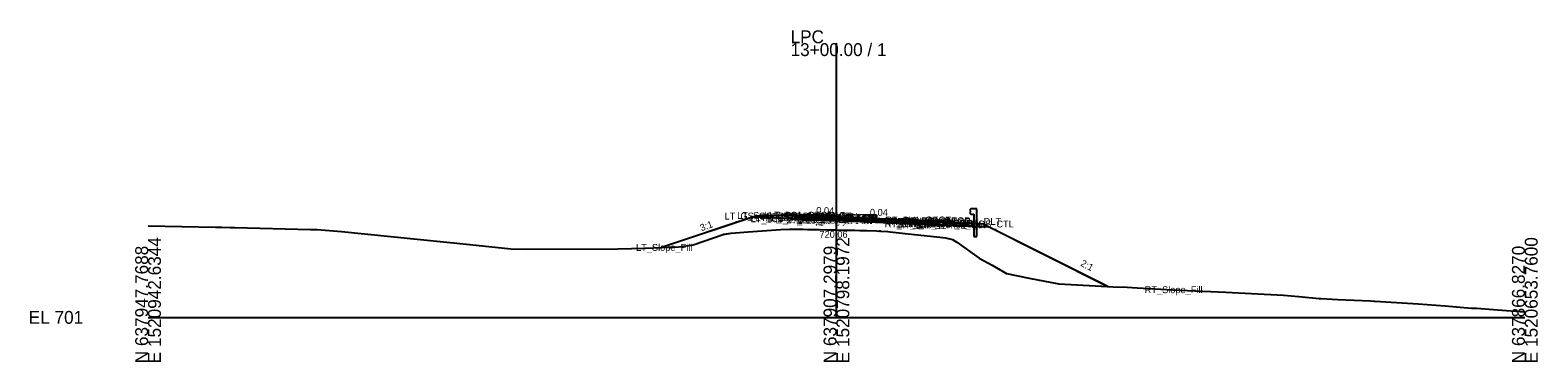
# Model space of a CAD drawing. Extents: x -26 to 303, y -10 to 4521.
# Drawn here: x -25.7 to 302.8, y 2990.3 to 3062.6 of the extents above; entities that cross this region are included whole.
import ezdxf

# ---------------------------------------------------------------- set-up
doc = ezdxf.new("R2010")
doc.units = 0
for name, color, linetype in [('Default', 7, 'Continuous'), ('Exist Cross Section Cell', 7, 'Continuous'), ('Exist XS Center Line Elevation Label', 7, 'Continuous'), ('Exist XS Ground Line', 7, 'Continuous'), ('Prop CMT Guardrail Graphics', 7, 'Continuous'), ('Prop CMT Pvmt Course 1', 7, 'Continuous'), ('Prop CMT Pvmt Course 2', 7, 'Continuous'), ('Prop CMT Pvmt Course 3', 7, 'Continuous'), ('Prop CMT Pvmt Surface', 7, 'Continuous'), ('Prop CMT Pvmt Surface Shoulder', 7, 'Continuous'), ('Prop CMT Shld Paved Course 1', 7, 'Continuous'), ('Prop CMT Shld Paved Course 2', 7, 'Continuous'), ('Prop CMT Shld Paved Course 3', 7, 'Continuous'), ('Prop CMT Slope Grass', 7, 'Continuous'), ('Prop CMT Subgrade Earthwork', 7, 'Continuous'), ('Prop XS Earthwork Shape', 7, 'Continuous'), ('Prop XS Shear Point Element', 7, 'Continuous')]:
    doc.layers.add(name, color=color, linetype=linetype)

msp = doc.modelspace()

# ---------------------------------------------------------------- linework, layer by layer
at = {"layer": 'Exist Cross Section Cell'}
for p, q in [((150, 3000), (150, 3059.75)), ((0, 3000), (150, 3000)), ((150, 3000), (300, 3000))]:
    msp.add_line(p, q, dxfattribs=at)
at = {"layer": 'Exist XS Ground Line'}
msp.add_lwpolyline([(0, 3019.92), (14.67, 3019.67), (16.1, 3019.64), (17.96, 3019.62), (18.33, 3019.61), (18.91, 3019.6), (35.42, 3019.16), (36.83, 3019.17), (42.14, 3018.71), (70.12, 3015.86), (79.08, 3014.96), (82.44, 3014.84), (102.36, 3014.94), (108.32, 3015.11), (115.64, 3015.35), (118.75, 3015.83), (125.3, 3018.08), (125.32, 3018.09), (125.33, 3018.09), (125.36, 3018.1), (127.06, 3018.33), (130.75, 3018.65), (137.87, 3019.12), (139.76, 3019.25), (140.14, 3019.23), (141.08, 3019.2), (141.4, 3019.2), (142.44, 3019.21), (142.74, 3019.2), (143.67, 3019.17), (145.33, 3019.14), (146.27, 3019.13), (147.93, 3019.1), (148.85, 3019.09), (150, 3019.06), (151.2, 3019.04), (151.43, 3019.04), (153.4, 3018.99), (154.02, 3018.97), (155.11, 3018.94), (156.61, 3018.9), (158.72, 3018.83), (159.21, 3018.82), (159.48, 3018.83), (159.51, 3018.83), (159.67, 3018.82), (161.12, 3018.73), (161.21, 3018.73), (161.73, 3018.66), (165.65, 3018.22), (171.91, 3017.52), (173.77, 3017.3), (175.29, 3016.98), (176.22, 3016.37), (181.12, 3012.93), (183.96, 3011.38), (187.08, 3009.58), (192, 3008.58), (198.46, 3007.32), (210.3, 3006.69), (213.38, 3006.55), (215.54, 3006.43), (223.32, 3006), (228.1, 3005.79), (228.96, 3005.74), (229.84, 3005.71), (234.83, 3005.47), (247.41, 3004.87), (250.76, 3004.53), (255.22, 3004.14), (255.41, 3004.12), (255.65, 3004.1), (259.27, 3003.93), (266.38, 3003.58), (267.13, 3003.54), (267.37, 3003.53), (276.78, 3002.97), (282.67, 3002.49), (288.41, 3002.04), (289.55, 3001.98), (294.04, 3001.63), (300, 3001.2)], dxfattribs=at)
at = {"layer": 'Prop CMT Guardrail Graphics'}
for points in [[(180.6, 3023.65), (179.27, 3023.65), (179, 3023.36)], [(179, 3023.36), (179.27, 3023.07)], [(179.27, 3023.07), (179, 3022.77)], [(179, 3022.77), (179.27, 3022.48), (179.94, 3022.48)], [(180.6, 3017.65), (180.6, 3023.65)], [(179.94, 3022.48), (179.94, 3017.65)], [(179.94, 3017.65), (180.6, 3017.65)]]:
    msp.add_lwpolyline(points, dxfattribs=at)
at = {"layer": 'Prop CMT Pvmt Course 1'}
for points in [[(150.09, 3021.91), (145.42, 3022.1)], [(145.42, 3022.1), (145.42, 3021.85)], [(145.42, 3021.85), (150.09, 3021.66)], [(150.09, 3021.66), (150.09, 3021.91)], [(150.09, 3021.91), (166.95, 3021.23)], [(150.09, 3021.66), (150.09, 3021.91)], [(166.95, 3020.98), (150.09, 3021.66)], [(166.95, 3021.23), (166.95, 3020.98)]]:
    msp.add_lwpolyline(points, dxfattribs=at)
msp.add_lwpolyline([(150.09, 3021.66), (150.09, 3021.78), (150.09, 3021.78), (150.09, 3021.66)], close=True, dxfattribs=at)
msp.add_lwpolyline([(150.09, 3021.66), (150.09, 3021.78), (150.09, 3021.78), (150.09, 3021.66)], close=True, dxfattribs=at)
at = {"layer": 'Prop CMT Pvmt Course 2'}
for points in [[(150.09, 3021.66), (145.42, 3021.85)], [(145.42, 3021.85), (145.42, 3021.52)], [(145.42, 3021.52), (150.09, 3021.33)], [(150.09, 3021.33), (150.09, 3021.66)], [(150.09, 3021.33), (150.09, 3021.66)], [(150.09, 3021.66), (166.95, 3020.98)], [(166.95, 3020.65), (150.09, 3021.33)], [(166.95, 3020.98), (166.95, 3020.65)]]:
    msp.add_lwpolyline(points, dxfattribs=at)
at = {"layer": 'Prop CMT Pvmt Course 3'}
for points in [[(150.09, 3021.33), (145.42, 3021.52)], [(145.42, 3021.52), (145.42, 3021.27)], [(145.42, 3021.27), (150.09, 3021.08)], [(150.09, 3021.08), (150.09, 3021.33)], [(150.09, 3021.33), (166.95, 3020.65)], [(150.09, 3021.08), (150.09, 3021.33)], [(166.95, 3020.4), (150.09, 3021.08)], [(166.95, 3020.65), (166.95, 3020.4)]]:
    msp.add_lwpolyline(points, dxfattribs=at)
at = {"layer": 'Prop CMT Pvmt Surface'}
for points in [[(150.09, 3021.91), (145.42, 3022.1)], [(150.09, 3021.91), (166.95, 3021.23)]]:
    msp.add_lwpolyline(points, dxfattribs=at)
at = {"layer": 'Prop CMT Pvmt Surface Shoulder'}
for points in [[(145.42, 3022.1), (141.43, 3022.26)], [(166.95, 3021.23), (170.94, 3021.07)]]:
    msp.add_lwpolyline(points, dxfattribs=at)
at = {"layer": 'Prop CMT Shld Paved Course 1'}
for p in [(171.21, 3020.81), (179, 3020.55)]:
    msp.add_line(p, (179, 3020.3), dxfattribs=at)
for points in [[(145.42, 3022.1), (141.43, 3022.26), (141.19, 3022.01)], [(141.19, 3022.01), (145.42, 3021.85)], [(145.42, 3021.85), (145.42, 3022.1)], [(166.95, 3021.23), (170.94, 3021.07), (171.21, 3020.81)], [(166.95, 3020.98), (166.95, 3021.23)], [(171.21, 3020.81), (166.95, 3020.98)]]:
    msp.add_lwpolyline(points, dxfattribs=at)
at = {"layer": 'Prop CMT Shld Paved Course 2'}
for points in [[(145.42, 3021.85), (141.19, 3022.01), (140.87, 3021.7)], [(140.87, 3021.7), (145.42, 3021.52)], [(145.42, 3021.52), (145.42, 3021.85)], [(166.95, 3020.98), (171.21, 3020.81), (171.55, 3020.47)], [(166.95, 3020.65), (166.95, 3020.98)], [(171.55, 3020.47), (166.95, 3020.65)]]:
    msp.add_lwpolyline(points, dxfattribs=at)
at = {"layer": 'Prop CMT Shld Paved Course 3'}
for p, q in [((140.87, 3021.7), (140.63, 3021.46)), ((171.55, 3020.47), (171.81, 3020.21))]:
    msp.add_line(p, q, dxfattribs=at)
for points in [[(140.13, 3021.48), (145.42, 3021.27)], [(145.42, 3021.52), (140.87, 3021.7), (140.63, 3021.46)], [(145.42, 3021.27), (145.42, 3021.52)], [(166.95, 3020.4), (166.95, 3020.65)], [(166.95, 3020.65), (171.55, 3020.47), (171.81, 3020.21)], [(172.31, 3020.19), (166.95, 3020.4)]]:
    msp.add_lwpolyline(points, dxfattribs=at)
at = {"layer": 'Prop CMT Slope Grass'}
for points in [[(141.43, 3022.26), (132.44, 3022.08), (111.91, 3015.23)], [(170.94, 3021.07), (181.96, 3020.36), (209.17, 3006.75)]]:
    msp.add_lwpolyline(points, dxfattribs=at)
at = {"layer": 'Prop CMT Subgrade Earthwork'}
for points in [[(145.42, 3021.27), (131.66, 3021.82)], [(150.09, 3021.08), (145.42, 3021.27)], [(150.09, 3021.08), (166.95, 3020.4)], [(166.95, 3020.4), (183.17, 3019.75)]]:
    msp.add_lwpolyline(points, dxfattribs=at)
at = {"layer": 'Prop XS Earthwork Shape'}
msp.add_lwpolyline([(141.08, 3019.2), (141.4, 3019.2), (142.44, 3019.21), (142.74, 3019.2), (143.67, 3019.17), (145.33, 3019.14), (146.27, 3019.13), (147.93, 3019.1), (148.85, 3019.09), (150, 3019.06), (151.2, 3019.04), (151.43, 3019.04), (153.4, 3018.99), (154.02, 3018.97), (155.11, 3018.94), (156.61, 3018.9), (158.72, 3018.83), (159.21, 3018.82), (159.51, 3018.83), (159.67, 3018.82), (161.12, 3018.73), (161.73, 3018.66), (165.65, 3018.22), (171.91, 3017.52), (173.77, 3017.3), (175.29, 3016.98), (176.22, 3016.37), (181.12, 3012.93), (183.96, 3011.38), (187.08, 3009.58), (192, 3008.58), (198.46, 3007.32), (209.17, 3006.75), (183.17, 3019.75), (166.95, 3020.4), (150.09, 3021.08), (145.42, 3021.27), (131.66, 3021.82), (111.91, 3015.23), (115.64, 3015.35), (118.75, 3015.83), (125.3, 3018.08), (127.06, 3018.33), (130.75, 3018.65), (137.87, 3019.12), (139.76, 3019.25), (140.14, 3019.23)], close=True, dxfattribs=at)

# ---------------------------------------------------------------- texts
at = {"layer": 'Default'}
msp.add_text('-', height=0.0001, dxfattribs=at).set_placement((0, 3000))
at = {"layer": 'Exist Cross Section Cell'}
for s, p in [('LPC', (140, 3059.75)), ('13+00.00 / 1', (140, 3056.95)), ('EL 701', (-26, 2998.6))]:
    msp.add_text(s, height=2.8, dxfattribs=at).set_placement(p)
for s, p in [('E 1520942.6344', (2.8, 2990)), ('E 1520798.1972', (152.8, 2990)), ('E 1520653.7600', (302.8, 2990)), ('N 637947.7688', (0, 2990)), ('N 637907.2979', (150, 2990)), ('N 637866.8270', (300, 2990))]:
    msp.add_text(s, height=2.8, rotation=90, dxfattribs=at).set_placement(p)
at = {"layer": 'Exist XS Center Line Elevation Label'}
for s, rotation, p in [('0.04', 358.8358, (145.59, 3022.57)), ('0.04', 358.8358, (157.28, 3022.16)), ('3:1', 19.8357, (120.59, 3018.75)), ('2:1', 332.3479, (203.04, 3011.32))]:
    msp.add_text(s, height=1.5, rotation=rotation, dxfattribs=at).set_placement(p)
msp.add_text('720.06', height=1.5, dxfattribs=at).set_placement((146.3, 3017.35))
at = {"layer": 'Prop XS Shear Point Element'}
for s, p in [('LT_GS_OS_CTL', (125.63, 3021.33)), ('LT_Sub_Trench_Out_DLT', (128.37, 3021.46)), ('LT_PS3_Shelf_Out', (132.36, 3020.97)), ('LT_PS2_OEOP', (134.87, 3021.26)), ('LT_PS1_OEOP', (135.29, 3021.51)), ('LT_PV2_OEOT', (139.04, 3021.1)), ('LT_PV1_OEOT', (139.22, 3021.35)), ('RT_PV1_OEEOP', (143.27, 3021.03)), ('LT_PV1_OEEOP', (143.36, 3021.03)), ('RT_PV1_IEEOP', (143.84, 3021.03)), ('LT_PV1_IEEOP', (143.93, 3021.03)), ('PV1_PGL', (146.29, 3021.16)), ('LT_Sub_Trench_Out', (131.3, 3020.73)), ('LT_PS3_OEOP', (134.55, 3020.95)), ('LT_PV3_OEOT', (139.04, 3020.77)), ('LT_Sub_OEOT', (139.08, 3020.52)), ('RT_PV2_OEEOP', (143.09, 3020.91)), ('RT_PV3_OEEOP', (143.09, 3020.58)), ('RT_Sub_OEEOP', (143.13, 3020.33)), ('LT_PV2_OEEOP', (143.18, 3020.91)), ('LT_PV3_OEEOP', (143.18, 3020.58)), ('LT_Sub_OEEOP', (143.21, 3020.33)), ('RT_PV2_IEEOP', (143.66, 3020.91)), ('LT_PV2_IEEOP', (143.75, 3020.91)), ('PV2_PGL', (146.11, 3020.91)), ('RT_PV2_OEOT', (160.48, 3020.23)), ('RT_PV3_OEOT', (160.48, 3019.9)), ('RT_Sub_OEOT', (160.51, 3019.65)), ('RT_PV1_OEOT', (160.66, 3020.48)), ('RT_Sub_Trench_Out_DLT', (161.91, 3020.16)), ('RT_Sub_Trench_Out', (163.38, 3019.44)), ('RT_PS3_Shelf_Out', (163.95, 3019.7)), ('RT_PS1_OEOP', (164.72, 3020.32)), ('RT_PS2_OEOP', (164.8, 3020.06)), ('RT_PS3_OEOP', (165.14, 3019.72)), ('RT_GS_OS_CTL', (173.04, 3019.6)), ('LT_Slope_Fill', (106.34, 3014.5)), ('RT_Slope_Fill', (217.17, 3005.28))]:
    msp.add_text(s, height=1.5, dxfattribs=at).set_placement(p)

doc.saveas('drawing.dxf')
